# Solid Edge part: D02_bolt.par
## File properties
Author: mokuno
Template: metric.par
Last saved by: edge
Revision: 36
Application: Solid Edge
Material: 鋼鉄, 鋼材
面のスタイル: Steel
塗りつぶしのスタイル: ANSI32(Steel)
バーチャルスタイル: 鋼鉄 ブラシ
Coef. of Thermal Exp: 0.0
Thermal Conductivity: 32.0
Specific Heat: 481.0
Modulus of Elasticity: 199947953000.0
Poisson's Ratio: 0.29
Yield Stress: 262000766.0
Ultimate Stress: 358527364.0
Elongation: 0.0
File Size: 0
Number of Sheets: 0
Number of Objects: 0
非切断部品: False
文書内容のタイプ: 0
Density: 8906
Accuracy: 0.99
Document Number: MP-101
Revision: 1
Project Name: Trolley Wheel Assembly
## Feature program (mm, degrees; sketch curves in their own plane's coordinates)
sketch for "unnamed RevolvedProtrusion 1" plane through (0, 0, 0) normal (0, -1, 0) x-axis (1, 0, 0)
  line (-36, 0) -> (-36, 6)
  line (-36, 6) -> (-6, 6)
  line (-6, 6) -> (-6, 12)
  line (-6, 12) -> (0, 12)
  line (0, 12) -> (0, 0)
  dimension (linear) = 36
  dimension (linear) = 6
revolve "unnamed RevolvedProtrusion 1" add full turn 360 deg about sketch line (0, 0) -> (-36, 0)
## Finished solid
Body 1: solid body, 5 faces, 4 edges, 0 vertices.
  Faces by surface: plane 3, cylinder 2
  Edges by curve: circle 4
Bounding box of the edges (mm): 36.000 x 24.000 x 24.000, from (-36, -12, -12) to (0, 12, 12).
Cylindrical faces by radius (mm): R6 x1, R12 x1
Planar faces by outward normal: +x 1, -x 2
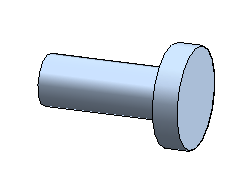
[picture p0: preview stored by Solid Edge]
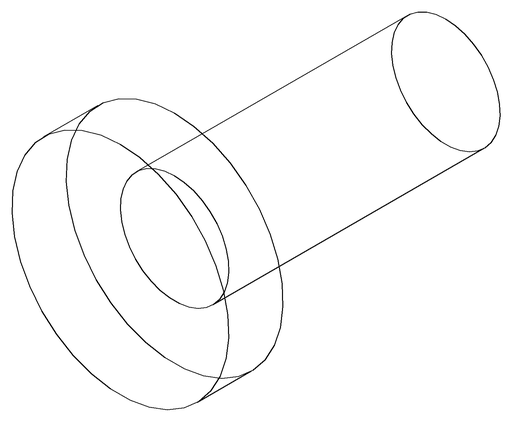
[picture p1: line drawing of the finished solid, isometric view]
